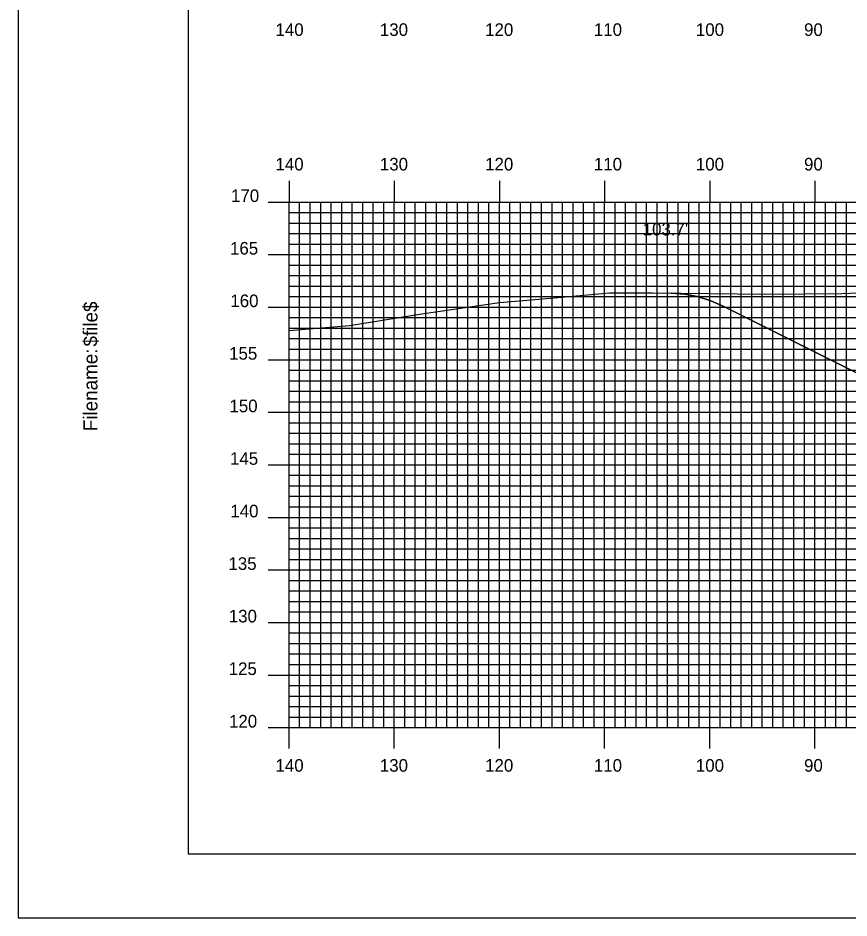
# Model space of a CAD drawing. Extents: x 1785008 to 1785352, y 442591 to 442811.
# Drawn here: x 1785008.2 to 1785087.3, y 442590.5 to 442676.2 of the extents above; entities that cross this region are included whole.
import ezdxf

# ---------------------------------------------------------------- set-up
doc = ezdxf.new("R2010")
doc.units = 0
for name, color, linetype in [('BORDER', 7, 'Continuous'), ('D_Roadway_Centerline', 7, 'Continuous'), ('D_Roadway_SlopeLines', 7, 'Continuous'), ('D_Text_Standard', 7, 'Continuous'), ('H_V ANNOTATION', 7, 'Continuous'), ('MAJOR', 7, 'Continuous'), ('MINOR', 7, 'Continuous'), ('PLOT BOUNDARY', 7, 'Continuous'), ('S_Roadway_Centerline', 7, 'Continuous')]:
    doc.layers.add(name, color=color, linetype=linetype)

msp = doc.modelspace()

# ---------------------------------------------------------------- linework, layer by layer
at = {"layer": 'BORDER'}
msp.add_lwpolyline([(1785024.426, 442596.665), (1785344.426, 442596.665), (1785344.426, 442806.665), (1785024.426, 442806.665)], close=True, dxfattribs=at)
at = {"layer": 'D_Roadway_Centerline'}
msp.add_lwpolyline([(1785070.375, 442649.994), (1785071.625, 442649.906), (1785072.875, 442649.664), (1785074.125, 442649.269), (1785075.375, 442648.721), (1785139.852, 442616.483), (1785143.852, 442617.483), (1785154.026, 442620.026), (1785162.026, 442620.346), (1785174.026, 442620.61), (1785186.026, 442620.874), (1785194.026, 442620.554), (1785204.2, 442618.011)], dxfattribs=at)
at = {"layer": 'D_Roadway_SlopeLines'}
msp.add_lwpolyline([(1785139.852, 442616.483), (1785075.375, 442648.721), (1785074.125, 442649.269), (1785072.875, 442649.664), (1785071.625, 442649.906), (1785070.375, 442649.994)], dxfattribs=at)
at = {"layer": 'MAJOR'}
for p, q in [((1785034.026, 442660.669), (1785034.026, 442658.665)), ((1785044.026, 442660.669), (1785044.026, 442658.665)), ((1785054.026, 442660.669), (1785054.026, 442658.665)), ((1785064.026, 442660.669), (1785064.026, 442658.665)), ((1785074.026, 442660.669), (1785074.026, 442658.665)), ((1785084.026, 442660.669), (1785084.026, 442658.665)), ((1785032.022, 442658.665), (1785034.026, 442658.665)), ((1785034.026, 442658.665), (1785314.026, 442658.665)), ((1785034.026, 442608.665), (1785034.026, 442658.665)), ((1785034.026, 442608.665), (1785034.026, 442658.665)), ((1785034.026, 442658.665), (1785314.026, 442658.665)), ((1785044.026, 442608.665), (1785044.026, 442658.665)), ((1785054.026, 442608.665), (1785054.026, 442658.665)), ((1785064.026, 442608.665), (1785064.026, 442658.665)), ((1785074.026, 442608.665), (1785074.026, 442658.665)), ((1785084.026, 442608.665), (1785084.026, 442658.665)), ((1785032.022, 442653.665), (1785034.026, 442653.665)), ((1785034.026, 442653.665), (1785314.026, 442653.665)), ((1785032.022, 442648.665), (1785034.026, 442648.665)), ((1785034.026, 442648.665), (1785314.026, 442648.665)), ((1785032.022, 442643.665), (1785034.026, 442643.665)), ((1785034.026, 442643.665), (1785314.026, 442643.665)), ((1785032.022, 442638.665), (1785034.026, 442638.665)), ((1785034.026, 442638.665), (1785314.026, 442638.665)), ((1785032.022, 442633.665), (1785034.026, 442633.665)), ((1785034.026, 442633.665), (1785314.026, 442633.665)), ((1785032.022, 442628.665), (1785034.026, 442628.665)), ((1785034.026, 442628.665), (1785314.026, 442628.665)), ((1785032.022, 442623.665), (1785034.026, 442623.665)), ((1785034.026, 442623.665), (1785314.026, 442623.665)), ((1785032.022, 442618.665), (1785034.026, 442618.665)), ((1785034.026, 442618.665), (1785314.026, 442618.665)), ((1785032.022, 442613.665), (1785034.026, 442613.665)), ((1785034.026, 442613.665), (1785314.026, 442613.665)), ((1785032.022, 442608.665), (1785034.026, 442608.665)), ((1785034.026, 442608.665), (1785314.026, 442608.665)), ((1785034.026, 442608.665), (1785314.026, 442608.665)), ((1785034.026, 442606.661), (1785034.026, 442608.665)), ((1785044.026, 442606.661), (1785044.026, 442608.665)), ((1785054.026, 442606.661), (1785054.026, 442608.665)), ((1785064.026, 442606.661), (1785064.026, 442608.665)), ((1785074.026, 442606.661), (1785074.026, 442608.665)), ((1785084.026, 442606.661), (1785084.026, 442608.665))]:
    msp.add_line(p, q, dxfattribs=at)
at = {"layer": 'MINOR'}
for p, q in [((1785035.026, 442608.665), (1785035.026, 442658.665)), ((1785036.026, 442608.665), (1785036.026, 442658.665)), ((1785037.026, 442608.665), (1785037.026, 442658.665)), ((1785038.026, 442608.665), (1785038.026, 442658.665)), ((1785039.026, 442608.665), (1785039.026, 442658.665)), ((1785040.026, 442608.665), (1785040.026, 442658.665)), ((1785041.026, 442608.665), (1785041.026, 442658.665)), ((1785042.026, 442608.665), (1785042.026, 442658.665)), ((1785043.026, 442608.665), (1785043.026, 442658.665)), ((1785045.026, 442608.665), (1785045.026, 442658.665)), ((1785046.026, 442608.665), (1785046.026, 442658.665)), ((1785047.026, 442608.665), (1785047.026, 442658.665)), ((1785048.026, 442608.665), (1785048.026, 442658.665)), ((1785049.026, 442608.665), (1785049.026, 442658.665)), ((1785050.026, 442608.665), (1785050.026, 442658.665)), ((1785051.026, 442608.665), (1785051.026, 442658.665)), ((1785052.026, 442608.665), (1785052.026, 442658.665)), ((1785053.026, 442608.665), (1785053.026, 442658.665)), ((1785055.026, 442608.665), (1785055.026, 442658.665)), ((1785056.026, 442608.665), (1785056.026, 442658.665)), ((1785057.026, 442608.665), (1785057.026, 442658.665)), ((1785058.026, 442608.665), (1785058.026, 442658.665)), ((1785059.026, 442608.665), (1785059.026, 442658.665)), ((1785060.026, 442608.665), (1785060.026, 442658.665)), ((1785061.026, 442608.665), (1785061.026, 442658.665)), ((1785062.026, 442608.665), (1785062.026, 442658.665)), ((1785063.026, 442608.665), (1785063.026, 442658.665)), ((1785065.026, 442608.665), (1785065.026, 442658.665)), ((1785066.026, 442608.665), (1785066.026, 442658.665)), ((1785067.026, 442608.665), (1785067.026, 442658.665)), ((1785068.026, 442608.665), (1785068.026, 442658.665)), ((1785069.026, 442608.665), (1785069.026, 442658.665)), ((1785070.026, 442608.665), (1785070.026, 442658.665)), ((1785071.026, 442608.665), (1785071.026, 442658.665)), ((1785072.026, 442608.665), (1785072.026, 442658.665)), ((1785073.026, 442608.665), (1785073.026, 442658.665)), ((1785075.026, 442608.665), (1785075.026, 442658.665)), ((1785076.026, 442608.665), (1785076.026, 442658.665)), ((1785077.026, 442608.665), (1785077.026, 442658.665)), ((1785078.026, 442608.665), (1785078.026, 442658.665)), ((1785079.026, 442608.665), (1785079.026, 442658.665)), ((1785080.026, 442608.665), (1785080.026, 442658.665)), ((1785081.026, 442608.665), (1785081.026, 442658.665)), ((1785082.026, 442608.665), (1785082.026, 442658.665)), ((1785083.026, 442608.665), (1785083.026, 442658.665)), ((1785085.026, 442608.665), (1785085.026, 442658.665)), ((1785086.026, 442608.665), (1785086.026, 442658.665)), ((1785087.026, 442608.665), (1785087.026, 442658.665)), ((1785034.026, 442657.665), (1785314.026, 442657.665)), ((1785034.026, 442657.665), (1785036.03, 442657.665)), ((1785034.026, 442656.665), (1785314.026, 442656.665)), ((1785034.026, 442656.665), (1785036.03, 442656.665)), ((1785034.026, 442655.665), (1785314.026, 442655.665)), ((1785034.026, 442655.665), (1785036.03, 442655.665)), ((1785034.026, 442654.665), (1785314.026, 442654.665)), ((1785034.026, 442654.665), (1785036.03, 442654.665)), ((1785034.026, 442652.665), (1785314.026, 442652.665)), ((1785034.026, 442652.665), (1785036.03, 442652.665)), ((1785034.026, 442651.665), (1785314.026, 442651.665)), ((1785034.026, 442651.665), (1785036.03, 442651.665)), ((1785034.026, 442650.665), (1785314.026, 442650.665)), ((1785034.026, 442650.665), (1785036.03, 442650.665)), ((1785034.026, 442649.665), (1785314.026, 442649.665)), ((1785034.026, 442649.665), (1785036.03, 442649.665)), ((1785034.026, 442647.665), (1785314.026, 442647.665)), ((1785034.026, 442647.665), (1785036.03, 442647.665)), ((1785034.026, 442646.665), (1785314.026, 442646.665)), ((1785034.026, 442646.665), (1785036.03, 442646.665)), ((1785034.026, 442645.665), (1785314.026, 442645.665)), ((1785034.026, 442645.665), (1785036.03, 442645.665)), ((1785034.026, 442644.665), (1785314.026, 442644.665)), ((1785034.026, 442644.665), (1785036.03, 442644.665)), ((1785034.026, 442642.665), (1785314.026, 442642.665)), ((1785034.026, 442642.665), (1785036.03, 442642.665)), ((1785034.026, 442641.665), (1785314.026, 442641.665)), ((1785034.026, 442641.665), (1785036.03, 442641.665)), ((1785034.026, 442640.665), (1785314.026, 442640.665)), ((1785034.026, 442640.665), (1785036.03, 442640.665)), ((1785034.026, 442639.665), (1785314.026, 442639.665)), ((1785034.026, 442639.665), (1785036.03, 442639.665)), ((1785034.026, 442637.665), (1785314.026, 442637.665)), ((1785034.026, 442637.665), (1785036.03, 442637.665)), ((1785034.026, 442636.665), (1785314.026, 442636.665)), ((1785034.026, 442636.665), (1785036.03, 442636.665)), ((1785034.026, 442635.665), (1785314.026, 442635.665)), ((1785034.026, 442635.665), (1785036.03, 442635.665)), ((1785034.026, 442634.665), (1785314.026, 442634.665)), ((1785034.026, 442634.665), (1785036.03, 442634.665)), ((1785034.026, 442632.665), (1785314.026, 442632.665)), ((1785034.026, 442632.665), (1785036.03, 442632.665)), ((1785034.026, 442631.665), (1785314.026, 442631.665)), ((1785034.026, 442631.665), (1785036.03, 442631.665)), ((1785034.026, 442630.665), (1785314.026, 442630.665)), ((1785034.026, 442630.665), (1785036.03, 442630.665)), ((1785034.026, 442629.665), (1785314.026, 442629.665)), ((1785034.026, 442629.665), (1785036.03, 442629.665)), ((1785034.026, 442627.665), (1785314.026, 442627.665)), ((1785034.026, 442627.665), (1785036.03, 442627.665)), ((1785034.026, 442626.665), (1785314.026, 442626.665)), ((1785034.026, 442626.665), (1785036.03, 442626.665)), ((1785034.026, 442625.665), (1785314.026, 442625.665)), ((1785034.026, 442625.665), (1785036.03, 442625.665)), ((1785034.026, 442624.665), (1785314.026, 442624.665)), ((1785034.026, 442624.665), (1785036.03, 442624.665)), ((1785034.026, 442622.665), (1785314.026, 442622.665)), ((1785034.026, 442622.665), (1785036.03, 442622.665)), ((1785034.026, 442621.665), (1785314.026, 442621.665)), ((1785034.026, 442621.665), (1785036.03, 442621.665)), ((1785034.026, 442620.665), (1785314.026, 442620.665)), ((1785034.026, 442620.665), (1785036.03, 442620.665)), ((1785034.026, 442619.665), (1785314.026, 442619.665)), ((1785034.026, 442619.665), (1785036.03, 442619.665)), ((1785034.026, 442617.665), (1785314.026, 442617.665)), ((1785034.026, 442617.665), (1785036.03, 442617.665)), ((1785034.026, 442616.665), (1785314.026, 442616.665)), ((1785034.026, 442616.665), (1785036.03, 442616.665)), ((1785034.026, 442615.665), (1785314.026, 442615.665)), ((1785034.026, 442615.665), (1785036.03, 442615.665)), ((1785034.026, 442614.665), (1785314.026, 442614.665)), ((1785034.026, 442614.665), (1785036.03, 442614.665)), ((1785034.026, 442612.665), (1785314.026, 442612.665)), ((1785034.026, 442612.665), (1785036.03, 442612.665)), ((1785034.026, 442611.665), (1785314.026, 442611.665)), ((1785034.026, 442611.665), (1785036.03, 442611.665)), ((1785034.026, 442610.665), (1785314.026, 442610.665)), ((1785034.026, 442610.665), (1785036.03, 442610.665)), ((1785034.026, 442609.665), (1785314.026, 442609.665)), ((1785034.026, 442609.665), (1785036.03, 442609.665))]:
    msp.add_line(p, q, dxfattribs=at)
at = {"layer": 'PLOT BOUNDARY'}
msp.add_lwpolyline([(1785008.239, 442590.547), (1785348.239, 442590.547), (1785348.239, 442810.547), (1785008.239, 442810.547)], close=True, dxfattribs=at)
at = {"layer": 'S_Roadway_Centerline'}
msp.add_lwpolyline([(1785034.026, 442646.43), (1785039.763, 442646.906), (1785046.633, 442648.038), (1785054.025, 442649.096), (1785058.885, 442649.508), (1785064.503, 442650.029), (1785066.265, 442650.03), (1785068.589, 442650.01), (1785079.342, 442649.913), (1785086.579, 442649.952), (1785088.111, 442650.022)], dxfattribs=at)

# ---------------------------------------------------------------- texts
at = {"layer": 'BORDER'}
for s, p in [('$file$', (1785015.795, 442644.916)), ('$file$', (1785015.795, 442644.916)), ('Filename:', (1785015.795, 442636.862)), ('Filename:', (1785015.795, 442636.862))]:
    msp.add_text(s, height=1.3392, rotation=90, dxfattribs=at).set_placement(p)
at = {"layer": 'D_Text_Standard'}
msp.add_text("103.7'", height=1.2, dxfattribs=at).set_placement((1785067.651, 442655.482))
at = {"layer": 'H_V ANNOTATION'}
for s, p in [('140', (1785032.73, 442674.465)), ('130', (1785042.655, 442674.465)), ('120', (1785052.666, 442674.465)), ('110', (1785063.009, 442674.465)), ('100', (1785072.709, 442674.465)), ('90', (1785082.998, 442674.465)), ('140', (1785032.73, 442661.665)), ('130', (1785042.655, 442661.665)), ('120', (1785052.666, 442661.665)), ('110', (1785063.009, 442661.665)), ('100', (1785072.709, 442661.665)), ('90', (1785082.998, 442661.665)), ('170', (1785028.499, 442658.665)), ('165', (1785028.403, 442653.665)), ('160', (1785028.435, 442648.665)), ('155', (1785028.317, 442643.665)), ('150', (1785028.349, 442638.665)), ('145', (1785028.403, 442633.665)), ('140', (1785028.435, 442628.665)), ('135', (1785028.253, 442623.665)), ('130', (1785028.285, 442618.665)), ('125', (1785028.275, 442613.665)), ('120', (1785028.307, 442608.665)), ('140', (1785032.73, 442604.465)), ('130', (1785042.655, 442604.465)), ('120', (1785052.666, 442604.465)), ('110', (1785063.009, 442604.465)), ('100', (1785072.709, 442604.465)), ('90', (1785082.998, 442604.465))]:
    msp.add_text(s, height=1.2, dxfattribs=at).set_placement(p)
at = {"layer": 'MAJOR'}
msp.add_text('-', height=0.012, dxfattribs=at).set_placement((1785034.017, 442608.665))

doc.saveas('drawing.dxf')
